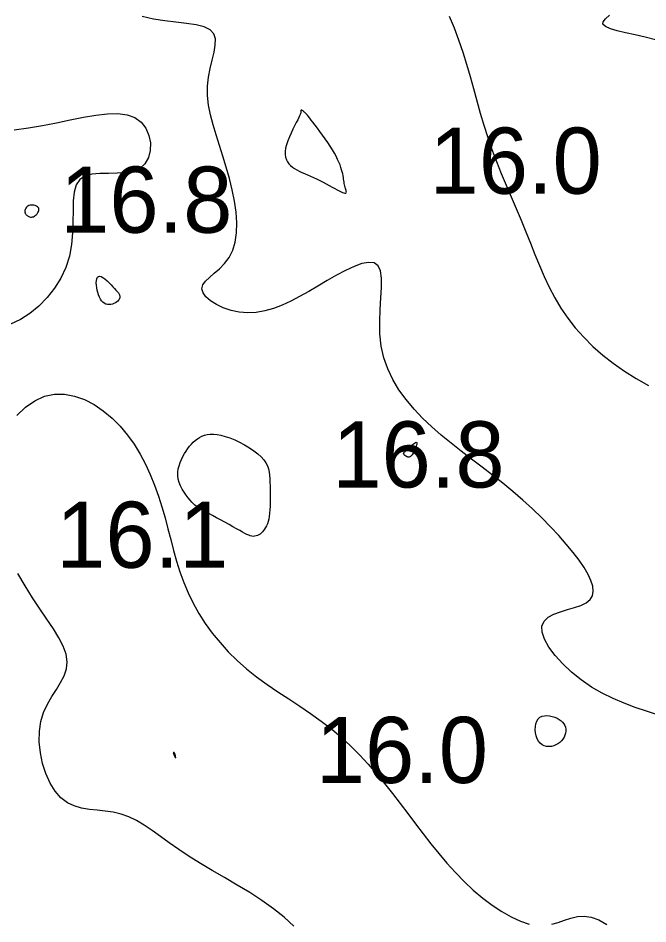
# Model space of a CAD drawing. Extents: x 3040093 to 3056816, y 408076 to 509144.
# Drawn here: x 3045596 to 3045643.6, y 434258.8 to 434327.2 of the extents above; entities that cross this region are included whole.
import ezdxf

# ---------------------------------------------------------------- set-up
doc = ezdxf.new("R2010")
doc.units = 0
doc.layers.add('V-CHAN-CONT-EL17', color=7, linetype='Continuous')
doc.layers.add('V-TOPO-SOUN-0610', color=7, linetype='Continuous')

msp = doc.modelspace()

# ---------------------------------------------------------------- linework, layer by layer
at = {"layer": 'V-CHAN-CONT-EL17'}
for points in [[(3045644.339, 434274.562), (3045643.508, 434274.839), (3045642.667, 434275.128), (3045641.824, 434275.444), (3045640.985, 434275.797), (3045640.158, 434276.202), (3045639.351, 434276.67), (3045638.574, 434277.209), (3045637.844, 434277.802), (3045637.183, 434278.428), (3045636.609, 434279.065), (3045636.145, 434279.692), (3045635.809, 434280.285), (3045635.623, 434280.824), (3045635.607, 434281.286), (3045635.77, 434281.657), (3045636.085, 434281.948), (3045636.512, 434282.178), (3045637.012, 434282.364), (3045637.546, 434282.525), (3045638.075, 434282.68), (3045638.561, 434282.847), (3045638.963, 434283.045), (3045639.252, 434283.287), (3045639.425, 434283.578), (3045639.49, 434283.915), (3045639.453, 434284.297), (3045639.32, 434284.723), (3045639.098, 434285.193), (3045638.794, 434285.705), (3045638.414, 434286.258), (3045637.965, 434286.85), (3045637.453, 434287.475), (3045636.884, 434288.123), (3045636.266, 434288.788), (3045635.604, 434289.462), (3045634.905, 434290.136), (3045634.176, 434290.803), (3045633.423, 434291.455), (3045632.652, 434292.086), (3045631.87, 434292.701), (3045631.083, 434293.304), (3045630.297, 434293.901), (3045629.517, 434294.499), (3045628.751, 434295.103), (3045628.004, 434295.719), (3045627.282, 434296.352), (3045626.592, 434297.009), (3045625.943, 434297.691), (3045625.346, 434298.402), (3045624.809, 434299.143), (3045624.342, 434299.916), (3045623.956, 434300.724), (3045623.659, 434301.569), (3045623.463, 434302.453), (3045623.369, 434303.373), (3045623.354, 434304.306), (3045623.388, 434305.222), (3045623.441, 434306.091), (3045623.482, 434306.886), (3045623.482, 434307.576), (3045623.409, 434308.132), (3045623.233, 434308.525), (3045622.933, 434308.736), (3045622.519, 434308.78), (3045622.01, 434308.683), (3045621.423, 434308.472), (3045620.778, 434308.171), (3045620.093, 434307.806), (3045619.387, 434307.404), (3045618.679, 434306.99), (3045617.983, 434306.586), (3045617.3, 434306.206), (3045616.63, 434305.858), (3045615.969, 434305.554), (3045615.315, 434305.302), (3045614.667, 434305.113), (3045614.022, 434304.996), (3045613.377, 434304.961), (3045612.736, 434305.014), (3045612.113, 434305.145), (3045611.53, 434305.34), (3045611.007, 434305.585), (3045610.564, 434305.865), (3045610.221, 434306.168), (3045609.999, 434306.479), (3045609.919, 434306.783), (3045609.991, 434307.072), (3045610.191, 434307.355), (3045610.488, 434307.645), (3045610.847, 434307.956), (3045611.236, 434308.303), (3045611.621, 434308.699), (3045611.971, 434309.157), (3045612.252, 434309.692), (3045612.439, 434310.312), (3045612.534, 434311.008), (3045612.548, 434311.766), (3045612.49, 434312.572), (3045612.373, 434313.41), (3045612.205, 434314.268), (3045611.996, 434315.131), (3045611.758, 434315.984), (3045611.502, 434316.816), (3045611.239, 434317.626), (3045610.985, 434318.414), (3045610.754, 434319.183), (3045610.558, 434319.934), (3045610.412, 434320.668), (3045610.33, 434321.386), (3045610.325, 434322.09), (3045610.404, 434322.779), (3045610.54, 434323.445), (3045610.695, 434324.078), (3045610.836, 434324.666), (3045610.927, 434325.2), (3045610.933, 434325.67), (3045610.817, 434326.064), (3045610.545, 434326.373), (3045610.093, 434326.592), (3045609.486, 434326.741), (3045608.761, 434326.847), (3045607.954, 434326.936), (3045607.102, 434327.034), (3045606.242, 434327.167), (3045605.41, 434327.362)], [(3045628.59, 434327.403), (3045628.971, 434326.502), (3045629.315, 434325.596), (3045629.626, 434324.683), (3045629.911, 434323.765), (3045630.179, 434322.843), (3045630.436, 434321.918), (3045630.691, 434320.993), (3045630.951, 434320.069), (3045631.224, 434319.147), (3045631.518, 434318.229), (3045631.837, 434317.316), (3045632.179, 434316.409), (3045632.538, 434315.508), (3045632.909, 434314.613), (3045633.285, 434313.724), (3045633.662, 434312.842), (3045634.034, 434311.967), (3045634.394, 434311.099), (3045634.741, 434310.238), (3045635.082, 434309.387), (3045635.426, 434308.546), (3045635.784, 434307.717), (3045636.166, 434306.904), (3045636.582, 434306.107), (3045637.042, 434305.328), (3045637.557, 434304.569), (3045638.133, 434303.832), (3045638.77, 434303.119), (3045639.464, 434302.433), (3045640.211, 434301.776), (3045641.008, 434301.151), (3045641.851, 434300.558), (3045642.736, 434300.002), (3045643.661, 434299.484)], [(3045644.198, 434325.606), (3045643.418, 434325.802), (3045642.655, 434325.977), (3045641.94, 434326.138), (3045641.308, 434326.292), (3045640.79, 434326.445), (3045640.419, 434326.605), (3045640.227, 434326.779), (3045640.235, 434326.974), (3045640.414, 434327.199), (3045640.721, 434327.465)], [(3045595.724, 434318.803), (3045596.801, 434318.95), (3045597.875, 434319.133), (3045598.934, 434319.342), (3045599.967, 434319.556), (3045600.961, 434319.754), (3045601.901, 434319.913), (3045602.774, 434320.013), (3045603.567, 434320.03), (3045604.265, 434319.943), (3045604.856, 434319.73), (3045605.329, 434319.379), (3045605.68, 434318.917), (3045605.909, 434318.381), (3045606.017, 434317.808), (3045606.003, 434317.234), (3045605.867, 434316.697), (3045605.609, 434316.234), (3045605.229, 434315.881), (3045604.732, 434315.663), (3045604.146, 434315.554), (3045603.505, 434315.515), (3045602.844, 434315.509), (3045602.197, 434315.497), (3045601.596, 434315.441), (3045601.077, 434315.302), (3045600.674, 434315.042), (3045600.408, 434314.633), (3045600.258, 434314.088), (3045600.19, 434313.43), (3045600.171, 434312.682), (3045600.166, 434311.867), (3045600.142, 434311.009), (3045600.066, 434310.131), (3045599.904, 434309.255), (3045599.63, 434308.403), (3045599.249, 434307.589), (3045598.774, 434306.822), (3045598.218, 434306.115), (3045597.595, 434305.479), (3045596.916, 434304.924), (3045596.195, 434304.462), (3045595.445, 434304.104)], [(3045595.927, 434297.209), (3045596.577, 434297.835), (3045597.277, 434298.323), (3045598.01, 434298.655), (3045598.763, 434298.816), (3045599.523, 434298.818), (3045600.282, 434298.676), (3045601.031, 434298.408), (3045601.76, 434298.029), (3045602.459, 434297.555), (3045603.119, 434297.004), (3045603.731, 434296.39), (3045604.287, 434295.729), (3045604.789, 434295.027), (3045605.241, 434294.292), (3045605.647, 434293.527), (3045606.011, 434292.739), (3045606.337, 434291.934), (3045606.628, 434291.117), (3045606.889, 434290.294), (3045607.125, 434289.47), (3045607.344, 434288.646), (3045607.556, 434287.824), (3045607.772, 434287.006), (3045608.002, 434286.192), (3045608.255, 434285.384), (3045608.541, 434284.583), (3045608.87, 434283.79), (3045609.251, 434283.007), (3045609.684, 434282.237), (3045610.167, 434281.482), (3045610.7, 434280.747), (3045611.281, 434280.032), (3045611.907, 434279.343), (3045612.579, 434278.681), (3045613.295, 434278.05), (3045614.051, 434277.451), (3045614.84, 434276.878), (3045615.652, 434276.322), (3045616.476, 434275.774), (3045617.303, 434275.227), (3045618.122, 434274.673), (3045618.925, 434274.103), (3045619.7, 434273.509), (3045620.441, 434272.884), (3045621.148, 434272.23), (3045621.826, 434271.55), (3045622.479, 434270.848), (3045623.109, 434270.126), (3045623.72, 434269.388), (3045624.317, 434268.637), (3045624.902, 434267.877), (3045625.481, 434267.111), (3045626.057, 434266.343), (3045626.635, 434265.579), (3045627.22, 434264.823), (3045627.818, 434264.079), (3045628.432, 434263.353), (3045629.068, 434262.648), (3045629.731, 434261.971), (3045630.422, 434261.327), (3045631.135, 434260.725), (3045631.858, 434260.178), (3045632.581, 434259.696), (3045633.292, 434259.29), (3045633.983, 434258.971), (3045634.642, 434258.752)], [(3045616.858, 434258.599), (3045616.126, 434259.271), (3045615.316, 434259.915), (3045614.442, 434260.534), (3045613.524, 434261.13), (3045612.581, 434261.707), (3045611.632, 434262.266), (3045610.698, 434262.812), (3045609.797, 434263.346), (3045608.948, 434263.873), (3045608.168, 434264.392), (3045607.448, 434264.896), (3045606.78, 434265.376), (3045606.15, 434265.822), (3045605.549, 434266.225), (3045604.965, 434266.574), (3045604.387, 434266.861), (3045603.804, 434267.076), (3045603.208, 434267.216), (3045602.605, 434267.302), (3045602.001, 434267.364), (3045601.405, 434267.429), (3045600.825, 434267.527), (3045600.269, 434267.685), (3045599.744, 434267.932), (3045599.26, 434268.297), (3045598.823, 434268.798), (3045598.441, 434269.418), (3045598.122, 434270.128), (3045597.873, 434270.902), (3045597.703, 434271.712), (3045597.619, 434272.529), (3045597.628, 434273.328), (3045597.739, 434274.079), (3045597.951, 434274.763), (3045598.24, 434275.386), (3045598.572, 434275.961), (3045598.914, 434276.501), (3045599.235, 434277.021), (3045599.501, 434277.533), (3045599.679, 434278.05), (3045599.738, 434278.587), (3045599.652, 434279.155), (3045599.435, 434279.758), (3045599.107, 434280.401), (3045598.69, 434281.086), (3045598.205, 434281.817), (3045597.672, 434282.598), (3045597.113, 434283.431), (3045596.55, 434284.32), (3045596.002, 434285.266)], [(3045636.351, 434258.738), (3045636.848, 434258.885), (3045637.329, 434259.054), (3045637.805, 434259.212), (3045638.29, 434259.324), (3045638.794, 434259.36), (3045639.331, 434259.284), (3045639.91, 434259.073), (3045640.526, 434258.734)]]:
    msp.add_lwpolyline(points, dxfattribs=at)
for points in [[(3045620.298, 434314.186), (3045620.432, 434314.12), (3045620.545, 434314.071), (3045620.637, 434314.036), (3045620.709, 434314.017), (3045620.763, 434314.013), (3045620.801, 434314.024), (3045620.823, 434314.05), (3045620.83, 434314.09), (3045620.826, 434314.144), (3045620.813, 434314.208), (3045620.792, 434314.283), (3045620.767, 434314.366), (3045620.74, 434314.456), (3045620.713, 434314.551), (3045620.689, 434314.65), (3045620.669, 434314.751), (3045620.653, 434314.855), (3045620.638, 434314.964), (3045620.623, 434315.079), (3045620.605, 434315.201), (3045620.583, 434315.332), (3045620.556, 434315.472), (3045620.52, 434315.623), (3045620.475, 434315.787), (3045620.419, 434315.963), (3045620.35, 434316.152), (3045620.268, 434316.354), (3045620.17, 434316.569), (3045620.057, 434316.798), (3045619.925, 434317.041), (3045619.774, 434317.299), (3045619.605, 434317.569), (3045619.42, 434317.849), (3045619.226, 434318.13), (3045619.028, 434318.409), (3045618.831, 434318.678), (3045618.642, 434318.931), (3045618.466, 434319.164), (3045618.308, 434319.369), (3045618.172, 434319.543), (3045618.058, 434319.687), (3045617.962, 434319.805), (3045617.881, 434319.901), (3045617.814, 434319.978), (3045617.757, 434320.04), (3045617.709, 434320.09), (3045617.665, 434320.133), (3045617.624, 434320.17), (3045617.586, 434320.204), (3045617.55, 434320.232), (3045617.518, 434320.256), (3045617.489, 434320.274), (3045617.464, 434320.287), (3045617.442, 434320.295), (3045617.424, 434320.297), (3045617.411, 434320.293), (3045617.401, 434320.284), (3045617.394, 434320.27), (3045617.39, 434320.254), (3045617.388, 434320.235), (3045617.388, 434320.214), (3045617.389, 434320.193), (3045617.391, 434320.171), (3045617.393, 434320.149), (3045617.393, 434320.123), (3045617.386, 434320.087), (3045617.37, 434320.036), (3045617.342, 434319.963), (3045617.298, 434319.864), (3045617.236, 434319.733), (3045617.153, 434319.565), (3045617.046, 434319.357), (3045616.922, 434319.114), (3045616.789, 434318.845), (3045616.653, 434318.559), (3045616.523, 434318.263), (3045616.407, 434317.967), (3045616.311, 434317.679), (3045616.243, 434317.407), (3045616.209, 434317.158), (3045616.209, 434316.932), (3045616.24, 434316.728), (3045616.298, 434316.544), (3045616.381, 434316.378), (3045616.487, 434316.229), (3045616.613, 434316.095), (3045616.755, 434315.974), (3045616.913, 434315.866), (3045617.083, 434315.767), (3045617.267, 434315.674), (3045617.462, 434315.584), (3045617.668, 434315.496), (3045617.884, 434315.404), (3045618.109, 434315.308), (3045618.343, 434315.204), (3045618.583, 434315.089), (3045618.827, 434314.968), (3045619.071, 434314.842), (3045619.31, 434314.715), (3045619.54, 434314.591), (3045619.758, 434314.473), (3045619.959, 434314.363), (3045620.14, 434314.267)], [(3045597.323, 434312.322), (3045597.395, 434312.387), (3045597.462, 434312.461), (3045597.518, 434312.542), (3045597.562, 434312.627), (3045597.59, 434312.711), (3045597.598, 434312.792), (3045597.584, 434312.867), (3045597.544, 434312.933), (3045597.483, 434312.989), (3045597.405, 434313.035), (3045597.315, 434313.07), (3045597.217, 434313.094), (3045597.115, 434313.106), (3045597.015, 434313.107), (3045596.921, 434313.095), (3045596.837, 434313.072), (3045596.764, 434313.038), (3045596.701, 434312.994), (3045596.647, 434312.944), (3045596.604, 434312.888), (3045596.571, 434312.829), (3045596.548, 434312.767), (3045596.534, 434312.706), (3045596.529, 434312.646), (3045596.533, 434312.589), (3045596.546, 434312.534), (3045596.567, 434312.481), (3045596.595, 434312.432), (3045596.63, 434312.385), (3045596.671, 434312.343), (3045596.719, 434312.304), (3045596.772, 434312.269), (3045596.83, 434312.24), (3045596.893, 434312.219), (3045596.959, 434312.206), (3045597.028, 434312.203), (3045597.1, 434312.212), (3045597.173, 434312.234), (3045597.248, 434312.27)], [(3045602.535, 434305.688), (3045602.43, 434305.773), (3045602.334, 434305.881), (3045602.247, 434306.01), (3045602.17, 434306.156), (3045602.102, 434306.318), (3045602.045, 434306.492), (3045601.999, 434306.675), (3045601.964, 434306.865), (3045601.941, 434307.055), (3045601.933, 434307.236), (3045601.942, 434307.4), (3045601.969, 434307.541), (3045602.016, 434307.65), (3045602.086, 434307.72), (3045602.179, 434307.742), (3045602.296, 434307.712), (3045602.433, 434307.636), (3045602.583, 434307.526), (3045602.74, 434307.391), (3045602.898, 434307.241), (3045603.051, 434307.085), (3045603.192, 434306.935), (3045603.315, 434306.8), (3045603.415, 434306.688), (3045603.495, 434306.598), (3045603.556, 434306.525), (3045603.601, 434306.466), (3045603.634, 434306.418), (3045603.658, 434306.376), (3045603.675, 434306.336), (3045603.688, 434306.296), (3045603.699, 434306.252), (3045603.707, 434306.204), (3045603.709, 434306.152), (3045603.703, 434306.096), (3045603.687, 434306.038), (3045603.658, 434305.978), (3045603.614, 434305.916), (3045603.553, 434305.853), (3045603.472, 434305.789), (3045603.376, 434305.729), (3045603.266, 434305.675), (3045603.147, 434305.631), (3045603.023, 434305.6), (3045602.896, 434305.587), (3045602.77, 434305.595), (3045602.649, 434305.628)], [(3045609.984, 434290.027), (3045609.82, 434290.116), (3045609.685, 434290.193), (3045609.57, 434290.266), (3045609.468, 434290.341), (3045609.369, 434290.426), (3045609.266, 434290.527), (3045609.15, 434290.652), (3045609.015, 434290.805), (3045608.867, 434290.984), (3045608.714, 434291.186), (3045608.562, 434291.407), (3045608.419, 434291.643), (3045608.294, 434291.889), (3045608.193, 434292.143), (3045608.124, 434292.4), (3045608.093, 434292.657), (3045608.097, 434292.912), (3045608.131, 434293.164), (3045608.192, 434293.411), (3045608.273, 434293.651), (3045608.372, 434293.883), (3045608.483, 434294.106), (3045608.601, 434294.319), (3045608.723, 434294.519), (3045608.849, 434294.707), (3045608.98, 434294.881), (3045609.116, 434295.042), (3045609.259, 434295.19), (3045609.41, 434295.324), (3045609.57, 434295.443), (3045609.739, 434295.547), (3045609.919, 434295.636), (3045610.111, 434295.708), (3045610.319, 434295.759), (3045610.545, 434295.787), (3045610.791, 434295.791), (3045611.06, 434295.767), (3045611.353, 434295.712), (3045611.674, 434295.625), (3045612.023, 434295.505), (3045612.39, 434295.354), (3045612.766, 434295.177), (3045613.14, 434294.98), (3045613.5, 434294.768), (3045613.837, 434294.544), (3045614.139, 434294.315), (3045614.396, 434294.085), (3045614.6, 434293.857), (3045614.755, 434293.63), (3045614.868, 434293.402), (3045614.946, 434293.17), (3045614.996, 434292.932), (3045615.026, 434292.684), (3045615.042, 434292.425), (3045615.051, 434292.152), (3045615.06, 434291.863), (3045615.067, 434291.562), (3045615.073, 434291.255), (3045615.076, 434290.947), (3045615.074, 434290.644), (3045615.067, 434290.351), (3045615.053, 434290.072), (3045615.031, 434289.814), (3045615.001, 434289.58), (3045614.962, 434289.371), (3045614.915, 434289.183), (3045614.86, 434289.015), (3045614.798, 434288.864), (3045614.73, 434288.73), (3045614.655, 434288.61), (3045614.575, 434288.502), (3045614.489, 434288.404), (3045614.399, 434288.317), (3045614.305, 434288.242), (3045614.207, 434288.18), (3045614.106, 434288.13), (3045614.003, 434288.095), (3045613.898, 434288.074), (3045613.792, 434288.068), (3045613.685, 434288.079), (3045613.572, 434288.107), (3045613.45, 434288.151), (3045613.313, 434288.213), (3045613.158, 434288.292), (3045612.979, 434288.389), (3045612.773, 434288.504), (3045612.534, 434288.638), (3045612.262, 434288.79), (3045611.962, 434288.955), (3045611.647, 434289.129), (3045611.325, 434289.304), (3045611.008, 434289.477), (3045610.706, 434289.641), (3045610.428, 434289.79), (3045610.185, 434289.92)], [(3045625.255, 434294.189), (3045625.233, 434294.207), (3045625.212, 434294.227), (3045625.192, 434294.248), (3045625.175, 434294.271), (3045625.162, 434294.294), (3045625.155, 434294.318), (3045625.155, 434294.341), (3045625.164, 434294.365), (3045625.181, 434294.391), (3045625.208, 434294.42), (3045625.245, 434294.454), (3045625.292, 434294.496), (3045625.35, 434294.546), (3045625.419, 434294.607), (3045625.499, 434294.682), (3045625.591, 434294.769), (3045625.69, 434294.863), (3045625.791, 434294.957), (3045625.889, 434295.044), (3045625.979, 434295.115), (3045626.057, 434295.165), (3045626.116, 434295.185), (3045626.153, 434295.169), (3045626.164, 434295.111), (3045626.151, 434295.017), (3045626.118, 434294.899), (3045626.069, 434294.763), (3045626.01, 434294.621), (3045625.943, 434294.48), (3045625.873, 434294.351), (3045625.803, 434294.242), (3045625.738, 434294.16), (3045625.679, 434294.104), (3045625.624, 434294.07), (3045625.574, 434294.053), (3045625.529, 434294.05), (3045625.489, 434294.057), (3045625.454, 434294.07), (3045625.423, 434294.084), (3045625.398, 434294.097), (3045625.376, 434294.108), (3045625.357, 434294.118), (3045625.34, 434294.127), (3045625.325, 434294.137), (3045625.309, 434294.148), (3045625.293, 434294.159), (3045625.275, 434294.173)], [(3045635.255, 434272.76), (3045635.178, 434272.974), (3045635.129, 434273.207), (3045635.108, 434273.446), (3045635.115, 434273.683), (3045635.153, 434273.905), (3045635.223, 434274.103), (3045635.324, 434274.267), (3045635.458, 434274.387), (3045635.618, 434274.466), (3045635.798, 434274.509), (3045635.991, 434274.518), (3045636.191, 434274.499), (3045636.39, 434274.457), (3045636.582, 434274.394), (3045636.761, 434274.315), (3045636.921, 434274.225), (3045637.059, 434274.124), (3045637.177, 434274.013), (3045637.272, 434273.893), (3045637.344, 434273.765), (3045637.394, 434273.63), (3045637.42, 434273.489), (3045637.422, 434273.343), (3045637.399, 434273.192), (3045637.354, 434273.04), (3045637.286, 434272.89), (3045637.198, 434272.746), (3045637.091, 434272.611), (3045636.966, 434272.488), (3045636.825, 434272.381), (3045636.67, 434272.294), (3045636.502, 434272.228), (3045636.326, 434272.187), (3045636.146, 434272.173), (3045635.966, 434272.188), (3045635.793, 434272.233), (3045635.631, 434272.311), (3045635.484, 434272.424), (3045635.357, 434272.574)], [(3045607.822, 434271.495), (3045607.839, 434271.458), (3045607.858, 434271.422), (3045607.876, 434271.389), (3045607.893, 434271.36), (3045607.908, 434271.339), (3045607.919, 434271.327), (3045607.928, 434271.326), (3045607.931, 434271.337), (3045607.931, 434271.36), (3045607.928, 434271.39), (3045607.922, 434271.427), (3045607.914, 434271.467), (3045607.905, 434271.509), (3045607.895, 434271.549), (3045607.886, 434271.585), (3045607.877, 434271.615), (3045607.869, 434271.64), (3045607.861, 434271.66), (3045607.854, 434271.676), (3045607.846, 434271.689), (3045607.839, 434271.698), (3045607.831, 434271.705), (3045607.822, 434271.711), (3045607.813, 434271.716), (3045607.803, 434271.719), (3045607.792, 434271.721), (3045607.783, 434271.722), (3045607.774, 434271.72), (3045607.766, 434271.717), (3045607.76, 434271.711), (3045607.755, 434271.703), (3045607.753, 434271.692), (3045607.754, 434271.678), (3045607.757, 434271.661), (3045607.762, 434271.642), (3045607.769, 434271.619), (3045607.779, 434271.593), (3045607.791, 434271.564), (3045607.805, 434271.531)]]:
    msp.add_lwpolyline(points, close=True, dxfattribs=at)

# ---------------------------------------------------------------- texts
at = {"layer": 'V-TOPO-SOUN-0610'}
for s, p in [('16.0 ', (3045627.123, 434313.97)), ('16.8 ', (3045599.203, 434311.02)), ('16.8 ', (3045619.773, 434291.76)), ('16.1 ', (3045598.903, 434285.69)), ('16.0 ', (3045618.523, 434269.42))]:
    msp.add_text(s, height=5, dxfattribs=at).set_placement(p)

doc.saveas('drawing.dxf')
